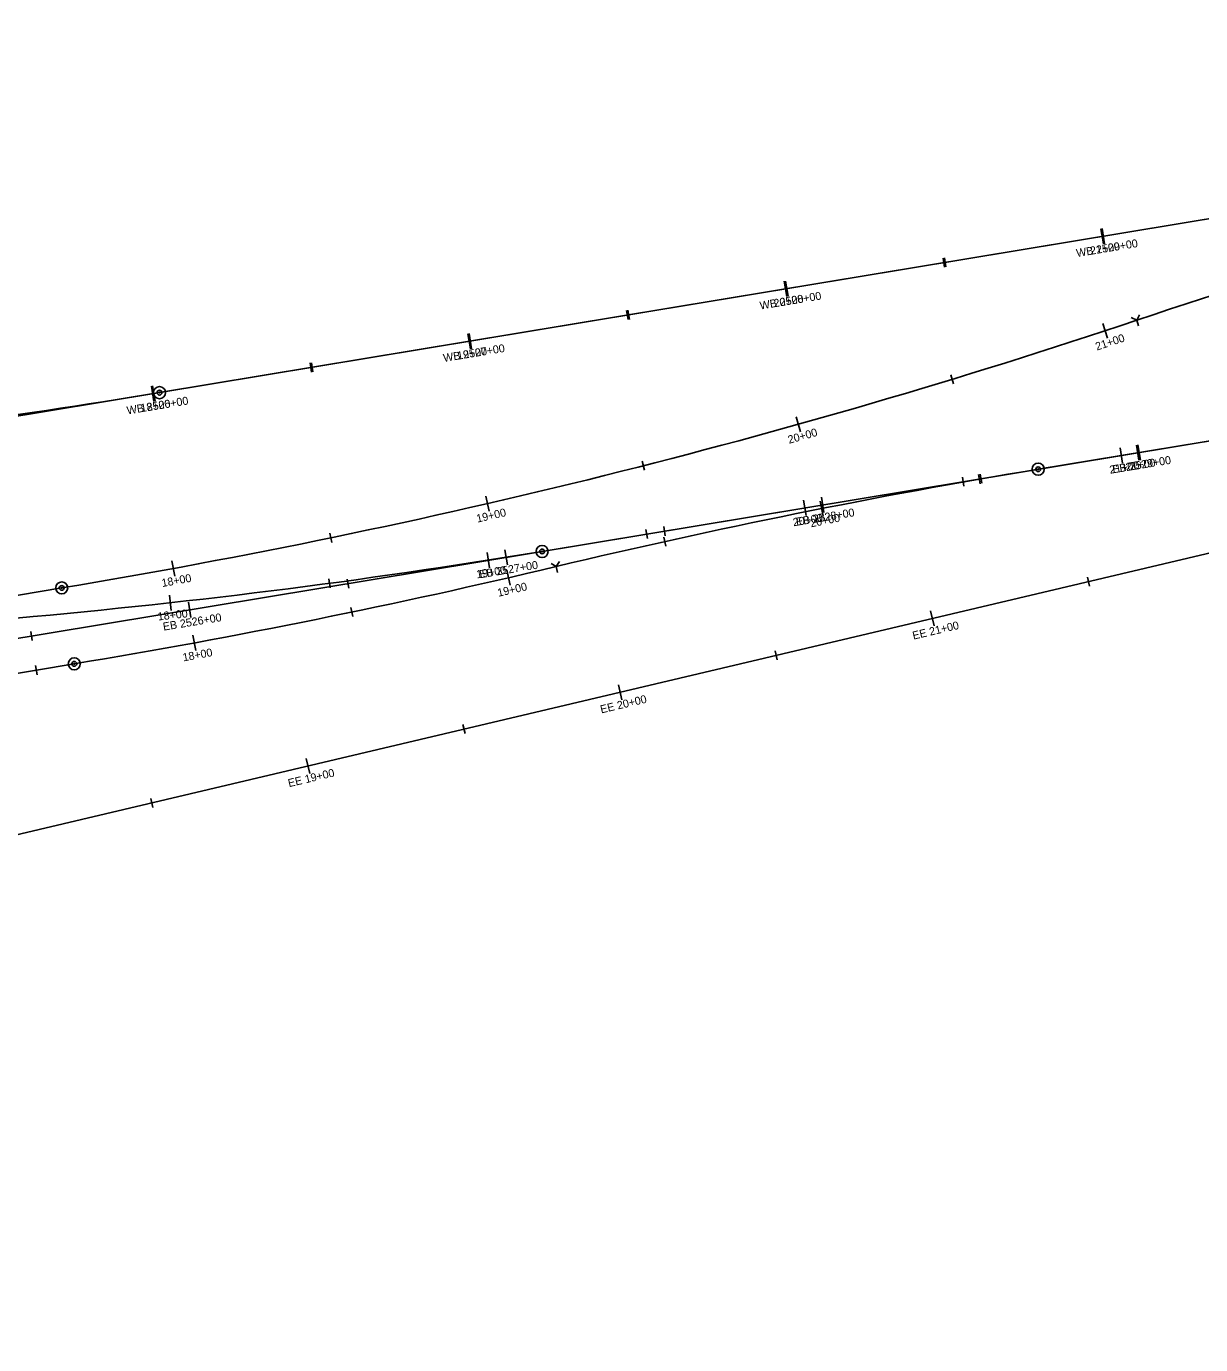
# Model space of a CAD drawing. Extents: x 950864 to 953360, y 1126381 to 1128045.
# Drawn here: x 952608.5 to 952974.5, y 1127119 to 1127530 of the extents above; entities that cross this region are included whole.
import ezdxf

# ---------------------------------------------------------------- set-up
doc = ezdxf.new("R2010")
doc.units = 0
for name, color, linetype in [('Existing', 7, 'Continuous'), ('LFILL_P', 7, 'Continuous'), ('North Crossover', 7, 'Continuous')]:
    doc.layers.add(name, color=color, linetype=linetype)

msp = doc.modelspace()

# ---------------------------------------------------------------- linework, layer by layer
at = {"layer": 'Existing'}
for p, q in [((950872.52, 1127121.15), (953338.85, 1127530.05)), ((950883.69, 1127053.72), (953350.03, 1127462.62)), ((952548.55, 1127264.51), (953008.86, 1127373.31))]:
    msp.add_line(p, q, dxfattribs=at)
for points in [[(952943.84, 1127466.99), (952944.63, 1127462.25)], [(952894.67, 1127457.87), (952895.14, 1127455.02)], [(952845.19, 1127450.63), (952845.98, 1127445.9)], [(952796.02, 1127441.51), (952796.49, 1127438.67)], [(952746.54, 1127434.28), (952747.32, 1127429.54)], [(952697.37, 1127425.15), (952697.84, 1127422.31)], [(952647.88, 1127417.92), (952648.67, 1127413.19)], [(952955.02, 1127399.56), (952955.81, 1127394.83)], [(952905.85, 1127390.44), (952906.32, 1127387.6)], [(952856.37, 1127383.21), (952857.15, 1127378.47)], [(952807.2, 1127374.08), (952807.67, 1127371.24)], [(952757.72, 1127366.85), (952758.5, 1127362.12)], [(952708.55, 1127357.73), (952709.02, 1127354.88)], [(952939.25, 1127358.34), (952939.91, 1127355.54)], [(952659.06, 1127350.49), (952659.85, 1127345.76)], [(952890.37, 1127347.77), (952891.48, 1127343.1)], [(952609.89, 1127341.37), (952610.36, 1127338.53)], [(952841.93, 1127335.34), (952842.6, 1127332.53)], [(952793.05, 1127324.77), (952794.16, 1127320.1)], [(952744.61, 1127312.33), (952745.28, 1127309.53)], [(952695.73, 1127301.77), (952696.84, 1127297.1)], [(952647.3, 1127289.33), (952647.96, 1127286.53)]]:
    msp.add_lwpolyline(points, dxfattribs=at)
at = {"layer": 'LFILL_P'}
for p, q in [((952923.92, 1127391.97), (953350.03, 1127462.62)), ((952954.63, 1127438.43), (952952.94, 1127439.27)), ((952955.47, 1127440.12), (952954.63, 1127438.43)), ((952954.63, 1127438.43), (952955.23, 1127436.64)), ((952773.7, 1127361.63), (952772.09, 1127362.62)), ((952774.68, 1127363.23), (952773.7, 1127361.63)), ((952773.7, 1127361.63), (952774.13, 1127359.8)), ((951976.7, 1127248.38), (952619.55, 1127354.96)), ((951901.7, 1127211.62), (952623.47, 1127331.29))]:
    msp.add_line(p, q, dxfattribs=at)
for points in [[(952944.04, 1127437.43), (952945.54, 1127432.87)], [(952896.72, 1127421.39), (952897.56, 1127418.64)], [(952848.5, 1127408.29), (952849.8, 1127403.67)], [(952954.53, 1127399.48), (952955.31, 1127394.75)], [(952800.49, 1127394.45), (952801.21, 1127391.66)], [(952905.36, 1127390.28), (952905.85, 1127387.44)], [(952751.73, 1127383.59), (952752.8, 1127378.91)], [(952855.99, 1127382.05), (952856.92, 1127377.34)], [(952703.13, 1127371.98), (952703.71, 1127369.16)], [(952807.21, 1127370.83), (952807.84, 1127368.02)], [(952653.91, 1127363.38), (952654.77, 1127358.66)], [(952758.27, 1127360.47), (952759.36, 1127355.79)], [(952709.68, 1127348.83), (952710.27, 1127346.01)], [(952660.47, 1127340.19), (952661.34, 1127335.47)], [(952611.4, 1127330.74), (952611.87, 1127327.9)]]:
    msp.add_lwpolyline(points, dxfattribs=at)
for centre, radius in [((952954.63, 1127438.43), 0.154), ((952923.92, 1127391.97), 1.89), ((952923.92, 1127391.97), 0.744), ((952923.92, 1127391.97), 0.154), ((952773.7, 1127361.63), 0.154), ((952619.55, 1127354.96), 1.88), ((952619.55, 1127354.96), 0.747), ((952619.55, 1127354.96), 0.156), ((952623.47, 1127331.29), 1.88), ((952623.47, 1127331.29), 0.747), ((952623.47, 1127331.29), 0.156)]:
    msp.add_circle(centre, radius, dxfattribs=at)
for centre, radius, start, end in [((953643.81, 1125386.05), 2165, 99.4135, 108.56188), ((952265.45, 1129490.81), 2165, 279.4135, 288.56188), ((953281.95, 1125232.45), 2189, 99.4135, 103.42571), ((952265.45, 1129490.81), 2189, 279.4135, 283.42571)]:
    msp.add_arc(centre, radius, start, end, dxfattribs=at)
at = {"layer": 'North Crossover'}
for p, q in [((952650.04, 1127415.85), (953338.85, 1127530.05)), ((952769.27, 1127366.33), (953350.03, 1127462.62))]:
    msp.add_line(p, q, dxfattribs=at)
for points in [[(952943.44, 1127466.92), (952944.23, 1127462.19)], [(952894.27, 1127457.8), (952894.75, 1127454.96)], [(952844.79, 1127450.57), (952845.58, 1127445.83)], [(952795.62, 1127441.44), (952796.09, 1127438.6)], [(952746.14, 1127434.21), (952746.92, 1127429.48)], [(952696.97, 1127425.09), (952697.44, 1127422.25)], [(952647.49, 1127417.86), (952648.27, 1127413.12)], [(952949.46, 1127398.64), (952950.24, 1127393.9)], [(952900.29, 1127389.51), (952900.76, 1127386.67)], [(952850.8, 1127382.28), (952851.59, 1127377.55)], [(952801.63, 1127373.16), (952802.1, 1127370.32)], [(952752.16, 1127366), (952752.91, 1127361.26)], [(952702.86, 1127357.83), (952703.25, 1127354.98)], [(952653.16, 1127352.72), (952653.69, 1127347.94)]]:
    msp.add_lwpolyline(points, dxfattribs=at)
for centre, radius in [((952650.04, 1127415.85), 1.89), ((952650.04, 1127415.85), 0.744), ((952650.04, 1127415.85), 0.154), ((952769.28, 1127366.33), 1.89), ((952769.28, 1127366.33), 0.744), ((952769.28, 1127366.33), 0.154)]:
    msp.add_circle(centre, radius, dxfattribs=at)
for centre, radius, start in [((952292.01, 1129575.37), 2189, 275.67597), ((952415.17, 1129502.18), 2165, 270.38393)]:
    msp.add_arc(centre, radius, start, 279.4135, dxfattribs=at)

# ---------------------------------------------------------------- texts
at = {"layer": 'Existing'}
for s, rotation, p in [('WB 2529+00', 9.4135, (952935.99, 1127458.1)), ('WB 2528+00', 9.4135, (952837.34, 1127441.74)), ('WB 2527+00', 9.4135, (952738.68, 1127425.39)), ('WB 2526+00', 9.4135, (952640.05, 1127409.03)), ('EB 2529+00', 9.4135, (952947.25, 1127390.68)), ('EB 2528+00', 9.4135, (952848.6, 1127374.33)), ('EB 2527+00', 9.4135, (952749.94, 1127357.97)), ('EB 2526+00', 9.4135, (952651.31, 1127341.62)), ('EE 21+00', 13.2987, (952885.05, 1127338.82)), ('EE 20+00', 13.2987, (952787.73, 1127315.82)), ('EE 19+00', 13.2987, (952690.41, 1127292.82))]:
    msp.add_text(s, height=2.496, rotation=rotation, dxfattribs=at).set_placement(p)
at = {"layer": 'LFILL_P'}
for s, rotation, p in [('21+00', 18.2875, (952942.21, 1127428.94)), ('20+00', 15.641, (952846.28, 1127399.89)), ('21+00', 9.4135, (952951.41, 1127391.37)), ('19+00', 12.9946, (952749.12, 1127375.3)), ('20+00', 11.2084, (952853.12, 1127373.85)), ('18+00', 10.3481, (952650.92, 1127355.23)), ('19+00', 13.0256, (952755.67, 1127352.18)), ('18+00', 10.4081, (952657.49, 1127332.03))]:
    msp.add_text(s, height=2.496, rotation=rotation, dxfattribs=at).set_placement(p)
at = {"layer": 'North Crossover'}
for s, rotation, p in [('21+00', 9.4135, (952940.32, 1127458.82)), ('20+00', 9.4135, (952841.67, 1127442.46)), ('19+00', 9.4135, (952743.02, 1127426.1)), ('18+00', 9.3561, (952644.36, 1127409.75)), ('21+00', 9.4135, (952946.34, 1127390.53)), ('20+00', 9.4135, (952847.68, 1127374.18)), ('19+00', 8.9646, (952748.97, 1127357.91)), ('18+00', 6.3182, (952649.61, 1127344.79))]:
    msp.add_text(s, height=2.496, rotation=rotation, dxfattribs=at).set_placement(p)

doc.saveas('drawing.dxf')
